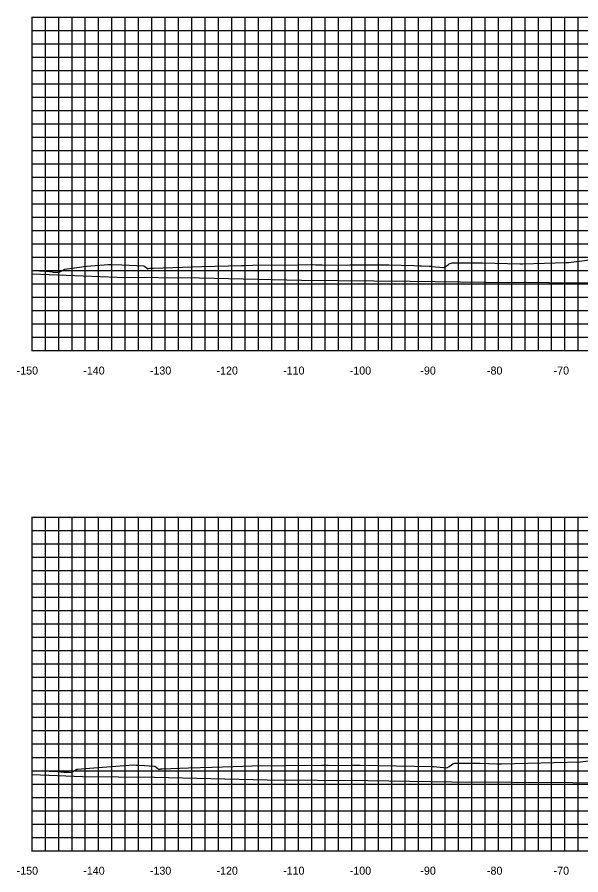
# Model space of a CAD drawing. Extents: x 1800880 to 1818864, y 245271 to 250560.
# Drawn here: x 1809596.2 to 1809680.8, y 249645.6 to 249774.2 of the extents above; entities that cross this region are included whole.
import ezdxf

# ---------------------------------------------------------------- set-up
doc = ezdxf.new("R2010")
doc.units = 0
for name, color, linetype in [('CL-CNST', 7, 'Continuous'), ('DESIGN - DRAINAGE - Bridges', 7, 'Continuous'), ('Level 46', 7, 'Continuous'), ('Level 62', 7, 'Continuous')]:
    doc.layers.add(name, color=color, linetype=linetype)

msp = doc.modelspace()

# ---------------------------------------------------------------- linework, layer by layer
at = {"layer": 'CL-CNST'}
for points in [[(1809598.46, 249736.22), (1809600.65, 249736.12), (1809601.49, 249736.01), (1809601.64, 249735.99), (1809602.1, 249735.99), (1809602.34, 249735.97), (1809602.63, 249736.01), (1809602.81, 249736.11), (1809603.38, 249736.44), (1809605.93, 249736.77), (1809606.18, 249736.8), (1809606.66, 249736.88), (1809609.96, 249737.11), (1809610.14, 249737.1), (1809610.51, 249737.1), (1809611.96, 249737.05), (1809615.23, 249736.92), (1809615.52, 249736.7), (1809615.85, 249736.46), (1809616.15, 249736.55), (1809616.16, 249736.55), (1809616.35, 249736.56), (1809616.55, 249736.56), (1809616.63, 249736.57), (1809624.01, 249736.8), (1809629.92, 249736.99), (1809630.32, 249736.99), (1809631.62, 249737.01), (1809638.49, 249737.08), (1809640.6, 249737.1), (1809641.06, 249737.09), (1809641.58, 249737.08), (1809642.03, 249737.08), (1809645.69, 249737.03), (1809646.15, 249737.08), (1809646.18, 249737.08), (1809648.67, 249737.07), (1809651.06, 249737.05), (1809652.04, 249737.05), (1809655.77, 249736.98), (1809656.69, 249736.94), (1809656.9, 249736.93), (1809658.09, 249736.87), (1809658.16, 249736.87), (1809658.26, 249736.86), (1809658.36, 249736.85), (1809658.44, 249736.84), (1809660.26, 249736.66), (1809660.69, 249736.94), (1809660.95, 249737.13), (1809661.09, 249737.24), (1809661.52, 249737.36), (1809664.43, 249737.36), (1809666.07, 249737.35), (1809671.66, 249737.22), (1809671.82, 249737.22), (1809672.15, 249737.22), (1809678.65, 249737.43), (1809678.98, 249737.43), (1809684.13, 249738.05)], [(1809598.46, 249661.27), (1809602.35, 249661.08), (1809603.22, 249661.02), (1809604.1, 249660.98), (1809604.36, 249660.95), (1809604.93, 249661.29), (1809605.11, 249661.4), (1809605.15, 249661.43), (1809605.29, 249661.43), (1809607.07, 249661.58), (1809613.62, 249662.08), (1809614.11, 249662.07), (1809614.55, 249662.07), (1809616.88, 249661.88), (1809617.35, 249661.56), (1809617.51, 249661.44), (1809617.68, 249661.47), (1809617.81, 249661.5), (1809617.97, 249661.52), (1809621.94, 249661.64), (1809625.49, 249661.75), (1809628.64, 249661.85), (1809631.52, 249661.94), (1809636.45, 249662), (1809641.96, 249662.06), (1809642.27, 249662.06), (1809642.64, 249662.06), (1809642.92, 249662.06), (1809646.2, 249662.02), (1809646.44, 249662.04), (1809646.47, 249662.04), (1809646.47, 249662.04), (1809646.5, 249662.04), (1809646.52, 249662.04), (1809646.56, 249662.04), (1809646.57, 249662.04), (1809646.61, 249662.04), (1809646.63, 249662.04), (1809646.66, 249662.04), (1809646.68, 249662.04), (1809646.72, 249662.04), (1809647.73, 249662.03), (1809658.55, 249661.85), (1809658.63, 249661.84), (1809658.72, 249661.83), (1809660.74, 249661.63), (1809661.09, 249661.85), (1809661.42, 249662.1), (1809661.61, 249662.24), (1809661.92, 249662.33), (1809665.15, 249662.34), (1809665.24, 249662.34), (1809665.71, 249662.35), (1809668.25, 249662.25), (1809668.35, 249662.25), (1809668.75, 249662.25), (1809668.91, 249662.25), (1809680.78, 249662.57), (1809685.27, 249663.09)]]:
    msp.add_lwpolyline(points, dxfattribs=at)
at = {"layer": 'DESIGN - DRAINAGE - Bridges'}
for p, q in [((1809598.4, 249774.22), (1809598.46, 249774.22)), ((1809598.46, 249724.22), (1809598.46, 249774.22)), ((1809598.4, 249764.22), (1809598.46, 249764.22)), ((1809598.4, 249754.22), (1809598.46, 249754.22)), ((1809598.4, 249744.22), (1809598.46, 249744.22)), ((1809598.4, 249734.22), (1809598.46, 249734.22)), ((1809598.4, 249724.22), (1809598.46, 249724.22)), ((1809598.46, 249724.22), (1809898.46, 249724.22)), ((1809598.46, 249724.16), (1809598.46, 249724.22)), ((1809608.46, 249724.16), (1809608.46, 249724.22)), ((1809618.46, 249724.16), (1809618.46, 249724.22)), ((1809628.46, 249724.16), (1809628.46, 249724.22)), ((1809638.46, 249724.16), (1809638.46, 249724.22)), ((1809648.46, 249724.16), (1809648.46, 249724.22)), ((1809658.46, 249724.16), (1809658.46, 249724.22)), ((1809668.46, 249724.16), (1809668.46, 249724.22)), ((1809678.46, 249724.16), (1809678.46, 249724.22)), ((1809598.4, 249699.22), (1809598.46, 249699.22)), ((1809598.46, 249649.22), (1809598.46, 249699.22)), ((1809598.4, 249689.22), (1809598.46, 249689.22)), ((1809598.4, 249679.22), (1809598.46, 249679.22)), ((1809598.4, 249669.22), (1809598.46, 249669.22)), ((1809598.4, 249659.22), (1809598.46, 249659.22)), ((1809598.4, 249649.22), (1809598.46, 249649.22)), ((1809598.46, 249649.22), (1809898.46, 249649.22)), ((1809598.46, 249649.16), (1809598.46, 249649.22)), ((1809608.46, 249649.16), (1809608.46, 249649.22)), ((1809618.46, 249649.16), (1809618.46, 249649.22)), ((1809628.46, 249649.16), (1809628.46, 249649.22)), ((1809638.46, 249649.16), (1809638.46, 249649.22)), ((1809648.46, 249649.16), (1809648.46, 249649.22)), ((1809658.46, 249649.16), (1809658.46, 249649.22)), ((1809668.46, 249649.16), (1809668.46, 249649.22)), ((1809678.46, 249649.16), (1809678.46, 249649.22))]:
    msp.add_line(p, q, dxfattribs=at)
at = {"layer": 'Level 46'}
for p, q in [((1809598.46, 249774.22), (1809898.46, 249774.22)), ((1809598.46, 249724.22), (1809598.46, 249774.22)), ((1809600.46, 249724.22), (1809600.46, 249774.22)), ((1809602.46, 249724.22), (1809602.46, 249774.22)), ((1809604.46, 249724.22), (1809604.46, 249774.22)), ((1809606.46, 249724.22), (1809606.46, 249774.22)), ((1809608.46, 249724.22), (1809608.46, 249774.22)), ((1809610.46, 249724.22), (1809610.46, 249774.22)), ((1809612.46, 249724.22), (1809612.46, 249774.22)), ((1809614.46, 249724.22), (1809614.46, 249774.22)), ((1809616.46, 249724.22), (1809616.46, 249774.22)), ((1809618.46, 249724.22), (1809618.46, 249774.22)), ((1809620.46, 249724.22), (1809620.46, 249774.22)), ((1809622.46, 249724.22), (1809622.46, 249774.22)), ((1809624.46, 249724.22), (1809624.46, 249774.22)), ((1809626.46, 249724.22), (1809626.46, 249774.22)), ((1809628.46, 249724.22), (1809628.46, 249774.22)), ((1809630.46, 249724.22), (1809630.46, 249774.22)), ((1809632.46, 249724.22), (1809632.46, 249774.22)), ((1809634.46, 249724.22), (1809634.46, 249774.22)), ((1809636.46, 249724.22), (1809636.46, 249774.22)), ((1809638.46, 249724.22), (1809638.46, 249774.22)), ((1809640.46, 249724.22), (1809640.46, 249774.22)), ((1809642.46, 249724.22), (1809642.46, 249774.22)), ((1809644.46, 249724.22), (1809644.46, 249774.22)), ((1809646.46, 249724.22), (1809646.46, 249774.22)), ((1809648.46, 249724.22), (1809648.46, 249774.22)), ((1809650.46, 249724.22), (1809650.46, 249774.22)), ((1809652.46, 249724.22), (1809652.46, 249774.22)), ((1809654.46, 249724.22), (1809654.46, 249774.22)), ((1809656.46, 249724.22), (1809656.46, 249774.22)), ((1809658.46, 249724.22), (1809658.46, 249774.22)), ((1809660.46, 249724.22), (1809660.46, 249774.22)), ((1809662.46, 249724.22), (1809662.46, 249774.22)), ((1809664.46, 249724.22), (1809664.46, 249774.22)), ((1809666.46, 249724.22), (1809666.46, 249774.22)), ((1809668.46, 249724.22), (1809668.46, 249774.22)), ((1809670.46, 249724.22), (1809670.46, 249774.22)), ((1809672.46, 249724.22), (1809672.46, 249774.22)), ((1809674.46, 249724.22), (1809674.46, 249774.22)), ((1809676.46, 249724.22), (1809676.46, 249774.22)), ((1809678.46, 249724.22), (1809678.46, 249774.22)), ((1809680.46, 249724.22), (1809680.46, 249774.22)), ((1809598.46, 249772.22), (1809898.46, 249772.22)), ((1809598.46, 249770.22), (1809898.46, 249770.22)), ((1809598.46, 249768.22), (1809898.46, 249768.22)), ((1809598.46, 249766.22), (1809898.46, 249766.22)), ((1809598.46, 249764.22), (1809898.46, 249764.22)), ((1809598.46, 249762.22), (1809898.46, 249762.22)), ((1809598.46, 249760.22), (1809898.46, 249760.22)), ((1809598.46, 249758.22), (1809898.46, 249758.22)), ((1809598.46, 249756.22), (1809898.46, 249756.22)), ((1809598.46, 249754.22), (1809898.46, 249754.22)), ((1809598.46, 249752.22), (1809898.46, 249752.22)), ((1809598.46, 249750.22), (1809898.46, 249750.22)), ((1809598.46, 249748.22), (1809898.46, 249748.22)), ((1809598.46, 249746.22), (1809898.46, 249746.22)), ((1809598.46, 249744.22), (1809898.46, 249744.22)), ((1809598.46, 249742.22), (1809898.46, 249742.22)), ((1809598.46, 249740.22), (1809898.46, 249740.22)), ((1809598.46, 249738.22), (1809898.46, 249738.22)), ((1809598.46, 249736.22), (1809898.46, 249736.22)), ((1809598.46, 249734.22), (1809898.46, 249734.22)), ((1809598.46, 249732.22), (1809898.46, 249732.22)), ((1809598.46, 249730.22), (1809898.46, 249730.22)), ((1809598.46, 249728.22), (1809898.46, 249728.22)), ((1809598.46, 249726.22), (1809898.46, 249726.22)), ((1809598.46, 249724.22), (1809898.46, 249724.22)), ((1809598.46, 249699.22), (1809898.46, 249699.22)), ((1809598.46, 249649.22), (1809598.46, 249699.22)), ((1809600.46, 249649.22), (1809600.46, 249699.22)), ((1809602.46, 249649.22), (1809602.46, 249699.22)), ((1809604.46, 249649.22), (1809604.46, 249699.22)), ((1809606.46, 249649.22), (1809606.46, 249699.22)), ((1809608.46, 249649.22), (1809608.46, 249699.22)), ((1809610.46, 249649.22), (1809610.46, 249699.22)), ((1809612.46, 249649.22), (1809612.46, 249699.22)), ((1809614.46, 249649.22), (1809614.46, 249699.22)), ((1809616.46, 249649.22), (1809616.46, 249699.22)), ((1809618.46, 249649.22), (1809618.46, 249699.22)), ((1809620.46, 249649.22), (1809620.46, 249699.22)), ((1809622.46, 249649.22), (1809622.46, 249699.22)), ((1809624.46, 249649.22), (1809624.46, 249699.22)), ((1809626.46, 249649.22), (1809626.46, 249699.22)), ((1809628.46, 249649.22), (1809628.46, 249699.22)), ((1809630.46, 249649.22), (1809630.46, 249699.22)), ((1809632.46, 249649.22), (1809632.46, 249699.22)), ((1809634.46, 249649.22), (1809634.46, 249699.22)), ((1809636.46, 249649.22), (1809636.46, 249699.22)), ((1809638.46, 249649.22), (1809638.46, 249699.22)), ((1809640.46, 249649.22), (1809640.46, 249699.22)), ((1809642.46, 249649.22), (1809642.46, 249699.22)), ((1809644.46, 249649.22), (1809644.46, 249699.22)), ((1809646.46, 249649.22), (1809646.46, 249699.22)), ((1809648.46, 249649.22), (1809648.46, 249699.22)), ((1809650.46, 249649.22), (1809650.46, 249699.22)), ((1809652.46, 249649.22), (1809652.46, 249699.22)), ((1809654.46, 249649.22), (1809654.46, 249699.22)), ((1809656.46, 249649.22), (1809656.46, 249699.22)), ((1809658.46, 249649.22), (1809658.46, 249699.22)), ((1809660.46, 249649.22), (1809660.46, 249699.22)), ((1809662.46, 249649.22), (1809662.46, 249699.22)), ((1809664.46, 249649.22), (1809664.46, 249699.22)), ((1809666.46, 249649.22), (1809666.46, 249699.22)), ((1809668.46, 249649.22), (1809668.46, 249699.22)), ((1809670.46, 249649.22), (1809670.46, 249699.22)), ((1809672.46, 249649.22), (1809672.46, 249699.22)), ((1809674.46, 249649.22), (1809674.46, 249699.22)), ((1809676.46, 249649.22), (1809676.46, 249699.22)), ((1809678.46, 249649.22), (1809678.46, 249699.22)), ((1809680.46, 249649.22), (1809680.46, 249699.22)), ((1809598.46, 249697.22), (1809898.46, 249697.22)), ((1809598.46, 249695.22), (1809898.46, 249695.22)), ((1809598.46, 249693.22), (1809898.46, 249693.22)), ((1809598.46, 249691.22), (1809898.46, 249691.22)), ((1809598.46, 249689.22), (1809898.46, 249689.22)), ((1809598.46, 249687.22), (1809898.46, 249687.22)), ((1809598.46, 249685.22), (1809898.46, 249685.22)), ((1809598.46, 249683.22), (1809898.46, 249683.22)), ((1809598.46, 249681.22), (1809898.46, 249681.22)), ((1809598.46, 249679.22), (1809898.46, 249679.22)), ((1809598.46, 249677.22), (1809898.46, 249677.22)), ((1809598.46, 249675.22), (1809898.46, 249675.22)), ((1809598.46, 249673.22), (1809898.46, 249673.22)), ((1809598.46, 249671.22), (1809898.46, 249671.22)), ((1809598.46, 249669.22), (1809898.46, 249669.22)), ((1809598.46, 249667.22), (1809898.46, 249667.22)), ((1809598.46, 249665.22), (1809898.46, 249665.22)), ((1809598.46, 249663.22), (1809898.46, 249663.22)), ((1809598.46, 249661.22), (1809898.46, 249661.22)), ((1809598.46, 249659.22), (1809898.46, 249659.22)), ((1809598.46, 249657.22), (1809898.46, 249657.22)), ((1809598.46, 249655.22), (1809898.46, 249655.22)), ((1809598.46, 249653.22), (1809898.46, 249653.22)), ((1809598.46, 249651.22), (1809898.46, 249651.22)), ((1809598.46, 249649.22), (1809898.46, 249649.22))]:
    msp.add_line(p, q, dxfattribs=at)
at = {"layer": 'Level 62'}
for points in [[(1809598.46, 249735.72), (1809611.25, 249735.23), (1809623.59, 249735.11), (1809638.89, 249734.77), (1809655.22, 249734.63), (1809666.53, 249734.49), (1809685.64, 249734.37), (1809694.17, 249734.29), (1809715.32, 249734.19), (1809721.81, 249734.14), (1809744.54, 249734.06), (1809749.45, 249734.02), (1809773.42, 249733.98), (1809777.09, 249733.96), (1809802.07, 249733.96), (1809804.73, 249733.94), (1809830.55, 249733.98), (1809832.37, 249733.97), (1809858.89, 249734.05), (1809860.01, 249734.05), (1809887.13, 249734.18), (1809887.65, 249734.18), (1809898.46, 249734.24)], [(1809598.46, 249660.63), (1809606.04, 249660.34), (1809616.86, 249660.23), (1809633.77, 249659.85), (1809648.89, 249659.73), (1809661.5, 249659.57), (1809679.62, 249659.45), (1809689.23, 249659.36), (1809709.56, 249659.26), (1809716.96, 249659.21), (1809738.99, 249659.13), (1809744.69, 249659.08), (1809768.06, 249659.04), (1809772.42, 249659.02), (1809796.88, 249659.01), (1809800.15, 249658.99), (1809825.51, 249659.03), (1809827.88, 249659.01), (1809854, 249659.1), (1809855.61, 249659.09), (1809882.37, 249659.22), (1809883.34, 249659.22), (1809898.46, 249659.3)]]:
    msp.add_lwpolyline(points, dxfattribs=at)

# ---------------------------------------------------------------- texts
for s, p in [('-150', (1809596.15, 249720.62)), ('-140', (1809606.15, 249720.62)), ('-130', (1809616.15, 249720.62)), ('-120', (1809626.15, 249720.62)), ('-110', (1809636.15, 249720.62)), ('-100', (1809646.15, 249720.62)), ('-90', (1809656.75, 249720.62)), ('-80', (1809666.75, 249720.62)), ('-70', (1809676.75, 249720.62)), ('-150', (1809596.15, 249645.62)), ('-140', (1809606.15, 249645.62)), ('-130', (1809616.15, 249645.62)), ('-120', (1809626.15, 249645.62)), ('-110', (1809636.15, 249645.62)), ('-100', (1809646.15, 249645.62)), ('-90', (1809656.75, 249645.62)), ('-80', (1809666.75, 249645.62)), ('-70', (1809676.75, 249645.62))]:
    msp.add_text(s, height=1.2).set_placement(p)
at = {"layer": 'DESIGN - DRAINAGE - Bridges'}
for p in [(1809598.46, 249724.22), (1809598.46, 249649.22)]:
    msp.add_text('-', height=0.0001, dxfattribs=at).set_placement(p)

doc.saveas('drawing.dxf')
